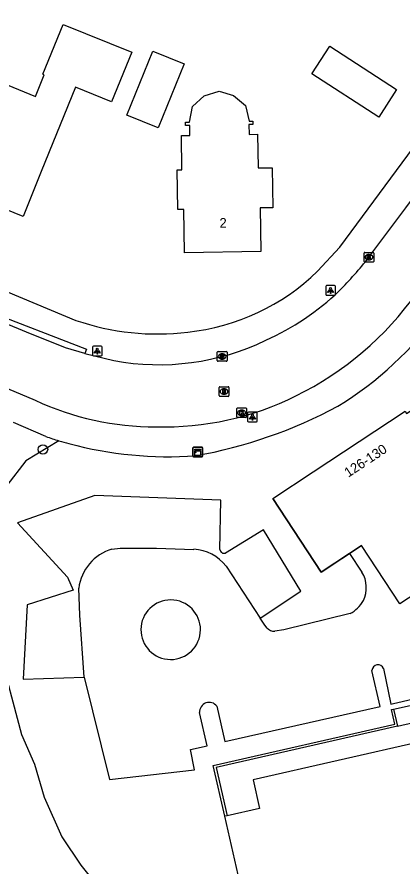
# Model space of a CAD drawing. Extents: x 161141 to 161601, y 381708 to 382245.
# Drawn here: x 161311.4 to 161351.2, y 381823.3 to 381911 of the extents above; entities that cross this region are included whole.
import ezdxf

# ---------------------------------------------------------------- set-up
doc = ezdxf.new("R2010")
doc.units = 0
for name, color, linetype in [('IMGEO_Boom', 7, 'Continuous'), ('IMGEO_Groenvoorziening', 7, 'Continuous'), ('IMGEO_Hek', 7, 'Continuous'), ('IMGEO_Kast', 7, 'Continuous'), ('IMGEO_Kolk', 7, 'Continuous'), ('IMGEO_Lichtpunt', 7, 'Continuous'), ('IMGEO_Muur', 7, 'Continuous'), ('IMGEO_Pand', 7, 'Continuous'), ('IMGEO_Pand_nummerreeks', 7, 'Continuous'), ('IMGEO_Parkeervlak_open', 7, 'Continuous'), ('IMGEO_Rijbaan_lokaal_open', 7, 'Continuous'), ('IMGEO_Rioolput', 7, 'Continuous'), ('IMGEO_Voetpad_op_trap', 7, 'Continuous'), ('IMGEO_Voetpad_open', 7, 'Continuous')]:
    doc.layers.add(name, color=color, linetype=linetype)

msp = doc.modelspace()

# ---------------------------------------------------------------- linework, layer by layer
at = {"layer": 'IMGEO_Boom'}
msp.add_circle((161314.117, 381866.376), 0.489, dxfattribs=at)
at = {"layer": 'IMGEO_Groenvoorziening'}
msp.add_lwpolyline([(161315.768, 381867.273), (161312.34, 381865.186), (161310.374, 381862.638), (161309.428, 381857.979), (161309.5, 381845.894), (161311.903, 381836.939), (161313.259, 381833.868), (161314.232, 381830.46), (161316.053, 381826.383), (161318.036, 381823.431), (161320.271, 381820.654), (161323.551, 381817.064), (161327.068, 381813.921)], dxfattribs=at)
at = {"layer": 'IMGEO_Hek'}
for points in [[(161337.847, 381861.294), (161342.013, 381864.045)], [(161337.847, 381861.294), (161342.849, 381853.685), (161346.996, 381856.469)]]:
    msp.add_lwpolyline(points, dxfattribs=at)
at = {"layer": 'IMGEO_Kast'}
for p, q in [((161329.603, 381865.684), (161329.603, 381866.525)), ((161329.603, 381866.525), (161329.603, 381865.684)), ((161329.678, 381866.609), (161330.519, 381866.609)), ((161330.519, 381866.609), (161329.678, 381866.609)), ((161330.603, 381866.534), (161330.603, 381865.693)), ((161330.603, 381865.693), (161330.603, 381866.534)), ((161330.528, 381865.609), (161329.687, 381865.609)), ((161329.687, 381865.609), (161330.528, 381865.609))]:
    msp.add_line(p, q, dxfattribs=at)
for points in [[(161329.798, 381866.399), (161330.398, 381866.399), (161330.398, 381866.314), (161329.798, 381866.314), (161329.798, 381866.399)], [(161329.798, 381866.224), (161330.398, 381866.224), (161330.398, 381865.735), (161329.798, 381865.735), (161329.798, 381866.224)]]:
    msp.add_lwpolyline(points, dxfattribs=at)
msp.add_circle((161329.882, 381866.073), 0.0377, dxfattribs=at)
for centre, start, end in [((161329.681, 381866.531), 92.4484, 184.28452), ((161329.681, 381866.531), 92.4484, 184.28452), ((161330.525, 381866.531), 2.4484, 94.28452), ((161330.525, 381866.531), 2.4484, 94.28452), ((161329.681, 381865.687), 182.4484, 274.28452), ((161329.681, 381865.687), 182.4484, 274.28452), ((161330.525, 381865.687), 272.4484, 4.28452), ((161330.525, 381865.687), 272.4484, 4.28452)]:
    msp.add_arc(centre, 0.0779, start, end, dxfattribs=at)
at = {"layer": 'IMGEO_Kolk'}
for p, q in [((161347.28, 381885.789), (161347.28, 381886.641)), ((161347.355, 381886.715), (161348.207, 381886.715)), ((161348.281, 381886.641), (161348.281, 381885.789)), ((161347.791, 381885.935), (161347.766, 381885.935)), ((161347.768, 381886.495), (161347.793, 381886.495)), ((161348.207, 381885.715), (161347.355, 381885.715)), ((161332.122, 381875.554), (161332.122, 381876.406)), ((161332.197, 381876.48), (161333.049, 381876.48)), ((161332.61, 381876.26), (161332.635, 381876.26)), ((161333.123, 381876.406), (161333.123, 381875.554)), ((161333.049, 381875.48), (161332.197, 381875.48)), ((161332.633, 381875.7), (161332.608, 381875.7)), ((161334.137, 381869.732), (161334.137, 381870.584)), ((161334.212, 381870.658), (161335.064, 381870.658)), ((161334.625, 381870.438), (161334.65, 381870.438)), ((161335.138, 381870.584), (161335.138, 381869.732)), ((161335.064, 381869.658), (161334.212, 381869.658)), ((161334.648, 381869.878), (161334.623, 381869.878))]:
    msp.add_line(p, q, dxfattribs=at)
for points in [[(161347.28, 381885.789), (161347.28, 381886.641)], [(161347.355, 381886.715), (161348.207, 381886.715)], [(161348.281, 381886.641), (161348.281, 381885.789)], [(161347.601, 381886.415), (161347.724, 381886.415), (161347.724, 381886.264), (161347.854, 381886.415), (161348.018, 381886.415), (161347.872, 381886.264), (161348.025, 381886.015), (161347.873, 381886.015), (161347.788, 381886.179), (161347.724, 381886.112), (161347.724, 381886.015), (161347.601, 381886.015), (161347.601, 381886.415)], [(161348.207, 381885.715), (161347.355, 381885.715)], [(161332.122, 381875.554), (161332.122, 381876.406)], [(161332.197, 381876.48), (161333.049, 381876.48)], [(161332.443, 381876.18), (161332.566, 381876.18), (161332.566, 381876.029), (161332.696, 381876.18), (161332.86, 381876.18), (161332.714, 381876.029), (161332.867, 381875.78), (161332.715, 381875.78), (161332.63, 381875.944), (161332.566, 381875.877), (161332.566, 381875.78), (161332.443, 381875.78), (161332.443, 381876.18)], [(161333.123, 381876.406), (161333.123, 381875.554)], [(161333.049, 381875.48), (161332.197, 381875.48)], [(161334.137, 381869.732), (161334.137, 381870.584)], [(161334.212, 381870.658), (161335.064, 381870.658)], [(161334.458, 381870.358), (161334.581, 381870.358), (161334.581, 381870.207), (161334.711, 381870.358), (161334.875, 381870.358), (161334.729, 381870.207), (161334.882, 381869.958), (161334.73, 381869.958), (161334.645, 381870.122), (161334.581, 381870.055), (161334.581, 381869.958), (161334.458, 381869.958), (161334.458, 381870.358)], [(161335.138, 381870.584), (161335.138, 381869.732)], [(161335.064, 381869.658), (161334.212, 381869.658)]]:
    msp.add_lwpolyline(points, dxfattribs=at)
for centre, start, end in [((161347.357, 381886.639), 91.55205, 178.44795), ((161347.357, 381886.639), 91.55205, 178.44795), ((161348.205, 381886.639), 1.55205, 88.44795), ((161348.205, 381886.639), 1.55205, 88.44795), ((161347.357, 381885.791), 181.55205, 268.44795), ((161347.357, 381885.791), 181.55205, 268.44795), ((161348.205, 381885.791), 271.55205, 358.44795), ((161348.205, 381885.791), 271.55205, 358.44795), ((161332.199, 381876.404), 91.55205, 178.44795), ((161332.199, 381876.404), 91.55205, 178.44795), ((161333.047, 381876.404), 1.55205, 88.44795), ((161333.047, 381876.404), 1.55205, 88.44795), ((161332.199, 381875.556), 181.55205, 268.44795), ((161332.199, 381875.556), 181.55205, 268.44795), ((161333.047, 381875.556), 271.55205, 358.44795), ((161333.047, 381875.556), 271.55205, 358.44795), ((161334.214, 381870.582), 91.55205, 178.44795), ((161334.214, 381870.582), 91.55205, 178.44795), ((161335.062, 381870.582), 1.55205, 88.44795), ((161335.062, 381870.582), 1.55205, 88.44795), ((161334.214, 381869.734), 181.55205, 268.44795), ((161334.214, 381869.734), 181.55205, 268.44795), ((161335.062, 381869.734), 271.55205, 358.44795), ((161335.062, 381869.734), 271.55205, 358.44795)]:
    msp.add_arc(centre, 0.0765, start, end, dxfattribs=at)
for centre, major_axis, ratio, start_param, end_param in [((161347.767, 381886.215), (-0.387, 0.002), 0.722429, 4.712389, 7.853982), ((161347.792, 381886.215), (-0.39, 0.002), 0.717154, 1.570796, 4.712389), ((161332.609, 381875.98), (-0.387, 0.002), 0.722429, 4.712389, 7.853982), ((161332.634, 381875.98), (-0.39, 0.002), 0.717154, 1.570796, 4.712389), ((161334.624, 381870.158), (-0.387, 0.002), 0.722429, 4.712389, 7.853982), ((161334.649, 381870.158), (-0.39, 0.002), 0.717154, 1.570796, 4.712389)]:
    msp.add_ellipse(centre, major_axis=major_axis, ratio=ratio, start_param=start_param, end_param=end_param, dxfattribs=at)
at = {"layer": 'IMGEO_Lichtpunt'}
for p, q in [((161343.32, 381883.193), (161343.32, 381882.386)), ((161343.32, 381883.193), (161343.32, 381882.386)), ((161344.222, 381883.288), (161343.414, 381883.288)), ((161344.222, 381883.288), (161343.414, 381883.288)), ((161344.316, 381882.386), (161344.316, 381883.193)), ((161344.316, 381882.386), (161344.316, 381883.193)), ((161343.414, 381882.292), (161344.222, 381882.292)), ((161343.414, 381882.292), (161344.222, 381882.292)), ((161320.131, 381877.025), (161319.323, 381877.025)), ((161320.131, 381877.025), (161319.323, 381877.025)), ((161319.229, 381876.93), (161319.229, 381876.123)), ((161319.229, 381876.93), (161319.229, 381876.123)), ((161320.225, 381876.123), (161320.225, 381876.93)), ((161320.225, 381876.123), (161320.225, 381876.93)), ((161319.323, 381876.029), (161320.131, 381876.029)), ((161319.323, 381876.029), (161320.131, 381876.029)), ((161335.255, 381870.115), (161335.255, 381869.308)), ((161335.255, 381870.115), (161335.255, 381869.308)), ((161336.157, 381870.21), (161335.349, 381870.21)), ((161336.157, 381870.21), (161335.349, 381870.21)), ((161336.251, 381869.308), (161336.251, 381870.115)), ((161336.251, 381869.308), (161336.251, 381870.115)), ((161335.349, 381869.214), (161336.157, 381869.214)), ((161335.349, 381869.214), (161336.157, 381869.214))]:
    msp.add_line(p, q, dxfattribs=at)
for points in [[(161343.694, 381882.857), (161343.733, 381882.829), (161343.545, 381882.567), (161343.507, 381882.594), (161343.694, 381882.857)], [(161343.796, 381882.809), (161343.843, 381882.809), (161343.843, 381882.487), (161343.796, 381882.487), (161343.796, 381882.809)], [(161343.906, 381882.829), (161343.944, 381882.856), (161344.131, 381882.594), (161344.092, 381882.566), (161343.906, 381882.829)], [(161319.603, 381876.594), (161319.642, 381876.566), (161319.454, 381876.304), (161319.416, 381876.331), (161319.603, 381876.594)], [(161319.705, 381876.546), (161319.752, 381876.546), (161319.752, 381876.224), (161319.705, 381876.224), (161319.705, 381876.546)], [(161319.815, 381876.566), (161319.853, 381876.593), (161320.04, 381876.331), (161320.001, 381876.303), (161319.815, 381876.566)], [(161335.629, 381869.779), (161335.668, 381869.751), (161335.48, 381869.489), (161335.442, 381869.516), (161335.629, 381869.779)], [(161335.731, 381869.731), (161335.778, 381869.731), (161335.778, 381869.409), (161335.731, 381869.409), (161335.731, 381869.731)], [(161335.841, 381869.751), (161335.879, 381869.778), (161336.066, 381869.516), (161336.027, 381869.488), (161335.841, 381869.751)]]:
    msp.add_lwpolyline(points, dxfattribs=at)
for centre in [(161343.819, 381882.991), (161319.728, 381876.728), (161335.754, 381869.913)]:
    msp.add_circle(centre, 0.0994, dxfattribs=at)
for centre, start, end in [((161343.414, 381883.193), 90, 180), ((161343.414, 381883.193), 90, 180), ((161344.222, 381883.193), 0, 90), ((161344.222, 381883.193), 0, 90), ((161343.414, 381882.386), 180, 270), ((161343.414, 381882.386), 180, 270), ((161344.222, 381882.386), 270, 0), ((161344.222, 381882.386), 270, 360), ((161319.323, 381876.93), 90, 180), ((161319.323, 381876.93), 90, 180), ((161320.131, 381876.93), 0, 90), ((161320.131, 381876.93), 0, 90), ((161319.323, 381876.123), 180, 270), ((161319.323, 381876.123), 180, 270), ((161320.131, 381876.123), 270, 0), ((161320.131, 381876.123), 270, 360), ((161335.349, 381870.115), 90, 180), ((161335.349, 381870.115), 90, 180), ((161336.157, 381870.115), 0, 90), ((161336.157, 381870.115), 0, 90), ((161335.349, 381869.308), 180, 270), ((161335.349, 381869.308), 180, 270), ((161336.157, 381869.308), 270, 0), ((161336.157, 381869.308), 270, 360)]:
    msp.add_arc(centre, 0.0946, start, end, dxfattribs=at)
at = {"layer": 'IMGEO_Muur'}
for points in [[(161332.909, 381828.491), (161331.707, 381833.726), (161350.437, 381838.001), (161350.1, 381839.503), (161350.325, 381839.554)], [(161350.325, 381839.554), (161350.722, 381837.807)], [(161350.722, 381837.807), (161331.995, 381833.545), (161333.143, 381828.544)]]:
    msp.add_lwpolyline(points, dxfattribs=at)
at = {"layer": 'IMGEO_Pand'}
for points in [[(161316.193, 381910.265), (161323.278, 381907.381), (161321.194, 381902.259), (161317.489, 381903.766), (161313.947, 381895.06), (161312.062, 381890.428), (161305.111, 381893.257), (161305.8, 381894.95), (161305.424, 381895.103), (161305.852, 381896.154), (161306.302, 381895.986), (161306.706, 381897.067), (161302.753, 381898.676), (161306.145, 381907.012), (161310.258, 381905.339), (161309.82, 381904.264), (161313.34, 381902.832), (161314.245, 381905.055), (161314.097, 381905.115), (161316.193, 381910.265)], [(161343.735, 381908.005), (161350.642, 381903.53), (161348.795, 381900.679), (161341.888, 381905.154), (161343.735, 381908.005)], [(161325.457, 381907.509), (161328.699, 381906.19), (161326.005, 381899.566), (161322.762, 381900.886), (161325.457, 381907.509)], [(161329.29, 381898.8), (161329.269, 381899.821), (161328.851, 381899.813), (161328.845, 381900.163), (161329.256, 381900.171), (161329.556, 381901.782), (161330.778, 381902.87), (161332.33, 381903.365), (161333.779, 381902.935), (161335.03, 381901.876), (161335.401, 381900.28), (161335.8, 381900.286), (161335.805, 381899.936), (161335.385, 381899.929), (161335.401, 381898.908), (161336.27, 381898.922), (161336.325, 381895.438), (161337.781, 381895.461), (161337.847, 381891.334), (161336.547, 381891.313), (161336.619, 381886.808), (161328.732, 381886.683), (161328.661, 381891.157), (161328.032, 381891.147), (161327.967, 381895.237), (161328.465, 381895.244), (161328.41, 381898.782), (161329.29, 381898.8)], [(161345.758, 381855.638), (161342.849, 381853.685), (161337.847, 381861.294), (161342.013, 381864.045), (161351.507, 381870.313), (161351.666, 381870.071), (161355.437, 381872.558)], [(161353.743, 381852.245), (161350.973, 381850.423), (161346.996, 381856.469), (161345.758, 381855.638)], [(161372.602, 381815.202), (161382.243, 381817.366), (161381.533, 381820.401), (161384.492, 381821.071), (161379.704, 381842.234), (161335.829, 381832.246), (161336.494, 381829.305), (161333.143, 381828.544)], [(161333.143, 381828.544), (161332.909, 381828.491)], [(161335.133, 381818.678), (161332.909, 381828.491)]]:
    msp.add_lwpolyline(points, dxfattribs=at)
at = {"layer": 'IMGEO_Parkeervlak_open'}
for points in [[(161332.376, 381856.03), (161332.496, 381861.126), (161319.475, 381861.603), (161311.484, 381858.803), (161316.642, 381853.17), (161317.245, 381851.856), (161312.502, 381850.329), (161312.056, 381842.659), (161318.365, 381842.85)], [(161336.534, 381848.967), (161340.753, 381851.735), (161336.879, 381858.07), (161332.951, 381855.667)]]:
    msp.add_lwpolyline(points, dxfattribs=at)
msp.add_arc((161332.824, 381856.103), 0.454, 189.20925, 286.26196, dxfattribs=at)
at = {"layer": 'IMGEO_Rijbaan_lokaal_open'}
for points in [[(161347.78, 381886.211), (161351.589, 381891.33), (161355.178, 381896.112), (161357.581, 381899.312), (161358.116, 381900.025), (161368.51, 381913.776), (161373.481, 381920.434), (161374.759, 381922.138), (161375.72, 381923.419)], [(161318.426, 381876.273), (161316.431, 381876.868), (161312.405, 381878.498), (161307.913, 381880.338)], [(161297.345, 381878.162), (161313.303, 381871.448)], [(161318.426, 381876.273), (161321.429, 381875.549)], [(161321.245, 381856.079), (161322.078, 381856.182), (161325.826, 381856.182), (161329.701, 381856.058)], [(161345.758, 381855.638), (161347.059, 381853.701)], [(161333.025, 381854.316), (161336.534, 381848.967)], [(161318.365, 381842.85), (161317.918, 381849.252), (161317.806, 381852.042)], [(161337.22, 381847.949), (161336.959, 381848.32), (161336.534, 381848.967)], [(161345.825, 381849.427), (161338.999, 381847.744), (161338.058, 381847.603)], [(161349.286, 381843.739), (161350.04, 381840.078), (161350.317, 381840.141), (161356.981, 381841.703), (161356.517, 381843.681)], [(161318.365, 381842.85), (161320.989, 381832.309), (161329.783, 381833.282), (161329.362, 381835.399), (161331.067, 381835.785), (161330.296, 381839.194)], [(161332.079, 381839.86), (161332.9, 381836.2), (161348.936, 381839.828), (161348.095, 381843.545)]]:
    msp.add_lwpolyline(points, dxfattribs=at)
for centre, radius, start, end in [((161314.604, 381912.547), 42.359, 315.28764, 321.55623), ((161326.251, 381901.996), 26.667, 294.07444, 313.79292), ((161325.528, 381901.818), 33.338, 296.19299, 324.65779), ((161326.071, 381900.593), 25.471, 259.49906, 295.73086), ((161326.635, 381899.193), 30.495, 268.42151, 296.50255), ((161325.661, 381897.966), 29.257, 245.01309, 270.26168), ((161322.625, 381851.42), 4.859, 106.50198, 172.64464), ((161329.478, 381851.59), 4.474, 37.54416, 87.1407), ((161344.416, 381852.089), 3.096, 334.60701, 31.38992), ((161327.306, 381847.761), 3.077, 83.7215, 263.7215), ((161327.306, 381847.761), 3.077, 263.7215, 83.7215), ((161344.149, 381852.56), 3.553, 298.14334, 329.58365), ((161338.056, 381848.787), 1.184, 225.04524, 270.08449), ((161348.711, 381843.519), 0.616, 20.9573, 177.54582), ((161331.284, 381839.269), 0.991, 36.6057, 184.35841)]:
    msp.add_arc(centre, radius, start, end, dxfattribs=at)
at = {"layer": 'IMGEO_Rioolput'}
for p, q in [((161332.319, 381871.926), (161332.319, 381872.778)), ((161332.394, 381872.852), (161333.246, 381872.852)), ((161332.807, 381872.632), (161332.832, 381872.632)), ((161333.32, 381872.778), (161333.32, 381871.926)), ((161333.246, 381871.852), (161332.394, 381871.852)), ((161332.83, 381872.072), (161332.805, 381872.072))]:
    msp.add_line(p, q, dxfattribs=at)
for points in [[(161332.319, 381871.926), (161332.319, 381872.778)], [(161332.394, 381872.852), (161333.246, 381872.852)], [(161333.32, 381872.778), (161333.32, 381871.926)], [(161333.246, 381871.852), (161332.394, 381871.852)], [(161332.908, 381872.55), (161332.656, 381872.552), (161332.656, 381872.152)], [(161332.656, 381872.152), (161332.78, 381872.152), (161332.78, 381872.314), (161332.791, 381872.314)], [(161332.834, 381872.471), (161332.78, 381872.471), (161332.78, 381872.39)], [(161332.78, 381872.39), (161332.832, 381872.39)], [(161332.838, 381872.285), (161332.909, 381872.152), (161333.049, 381872.152), (161332.984, 381872.278)]]:
    msp.add_lwpolyline(points, dxfattribs=at)
for centre, radius, start, end in [((161332.396, 381872.776), 0.0765, 91.55205, 178.44795), ((161332.396, 381872.776), 0.0765, 91.55205, 178.44795), ((161333.244, 381872.776), 0.0765, 1.55205, 88.44795), ((161333.244, 381872.776), 0.0765, 1.55205, 88.44795), ((161332.396, 381871.928), 0.0765, 181.55205, 268.44795), ((161332.396, 381871.928), 0.0765, 181.55205, 268.44795), ((161332.79, 381872.261), 0.0533, 26.02933, 88.69889), ((161332.816, 381872.579), 0.19, 274.7715, 282.96867), ((161332.84, 381872.375), 0.0964, 77.00612, 93.18647), ((161332.854, 381872.432), 0.0378, 276.66336, 79.67722), ((161332.907, 381872.44), 0.109, 350.36119, 89.41601), ((161332.905, 381872.44), 0.112, 277.58423, 350.98172), ((161332.889, 381872.225), 0.108, 29.51342, 73.79051), ((161333.244, 381871.928), 0.0765, 271.55205, 358.44795), ((161333.244, 381871.928), 0.0765, 271.55205, 358.44795)]:
    msp.add_arc(centre, radius, start, end, dxfattribs=at)
for centre, major_axis, ratio, start_param, end_param in [((161332.806, 381872.352), (-0.387, 0.002), 0.722429, 4.712389, 7.853982), ((161332.831, 381872.352), (-0.39, 0.002), 0.717154, 1.570796, 4.712389)]:
    msp.add_ellipse(centre, major_axis=major_axis, ratio=ratio, start_param=start_param, end_param=end_param, dxfattribs=at)
at = {"layer": 'IMGEO_Voetpad_op_trap'}
for points in [[(161350.325, 381839.554), (161355.298, 381840.668)], [(161350.722, 381837.807), (161355.696, 381838.933)]]:
    msp.add_lwpolyline(points, dxfattribs=at)
at = {"layer": 'IMGEO_Voetpad_open'}
for points in [[(161342.481, 381884.773), (161344.76, 381887.264), (161354.145, 381899.917), (161371.073, 381922.177), (161372.043, 381923.95)], [(161282.757, 381897.162), (161285.416, 381894.897), (161286.952, 381893.797), (161293.664, 381889.876), (161297.982, 381887.859), (161317.522, 381879.697)], [(161307.913, 381880.338), (161308.089, 381880.805), (161318.602, 381876.74), (161318.426, 381876.273)], [(161314.407, 381867.708), (161311.091, 381869.145)]]:
    msp.add_lwpolyline(points, dxfattribs=at)
for centre, radius, start, end in [((161326.709, 381900.982), 22.616, 275.98791, 314.21834), ((161326.096, 381901.218), 35.552, 301.32262, 324.6045), ((161325.898, 381903.973), 25.68, 250.9638, 277.09052), ((161321.407, 381913.724), 48.737, 279.98683, 298.38749), ((161326.802, 381904.141), 38.483, 251.21147, 253.3389), ((161326.209, 381902.06), 36.321, 253.29369, 254.99107), ((161327.026, 381904.852), 39.228, 254.89445, 274.14164)]:
    msp.add_arc(centre, radius, start, end, dxfattribs=at)

# ---------------------------------------------------------------- texts
at = {"layer": 'IMGEO_Pand_nummerreeks'}
for s, rotation, p in [('2', 0.908, (161332.358, 381889.261)), ('126-130', 33.43209, (161345.649, 381863.45))]:
    msp.add_text(s, height=1, rotation=rotation, dxfattribs=at).set_placement(p)

doc.saveas('drawing.dxf')
